// Mitsubishi GX Works2 project: MINI-15MR-2MTS-AC   PLC: FX1S

PROGRAM MAIN
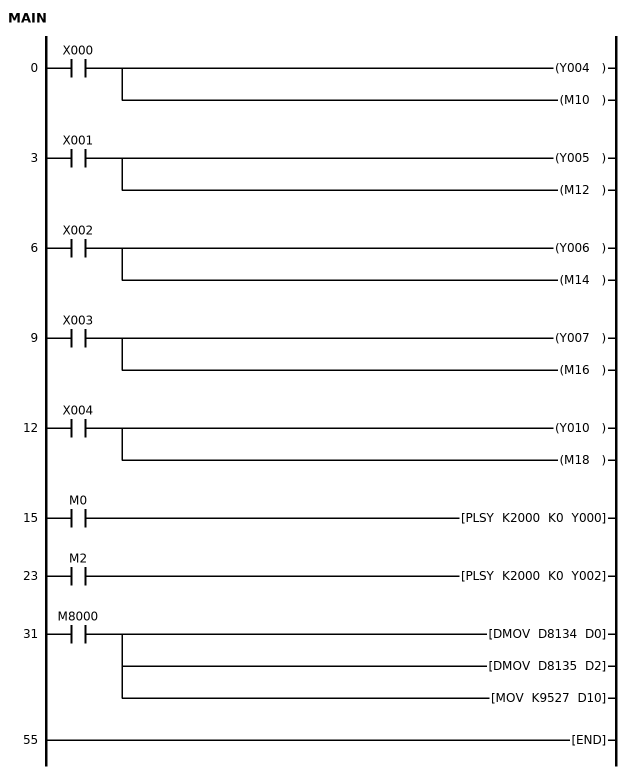
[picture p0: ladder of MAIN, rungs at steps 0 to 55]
0     LD      X000
      OUT     Y004
      OUT     M10
3     LD      X001
      OUT     Y005
      OUT     M12
6     LD      X002
      OUT     Y006
      OUT     M14
9     LD      X003
      OUT     Y007
      OUT     M16
12    LD      X004
      OUT     Y010
      OUT     M18
15    LD      M0
      PLSY    K2000 K0 Y000
23    LD      M2
      PLSY    K2000 K0 Y002
31    LD      M8000
      DMOV    D8134 D0
      DMOV    D8135 D2
      MOV     K9527 D10
55    END
END_PROGRAM
